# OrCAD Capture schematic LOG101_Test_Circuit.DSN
size A; title: LOG101, Precision LOGARITHMIC AND LOG RATIO AMPLIFIER; rev: 1.1; note: Datasheet: SBOS242B EVM: N/A
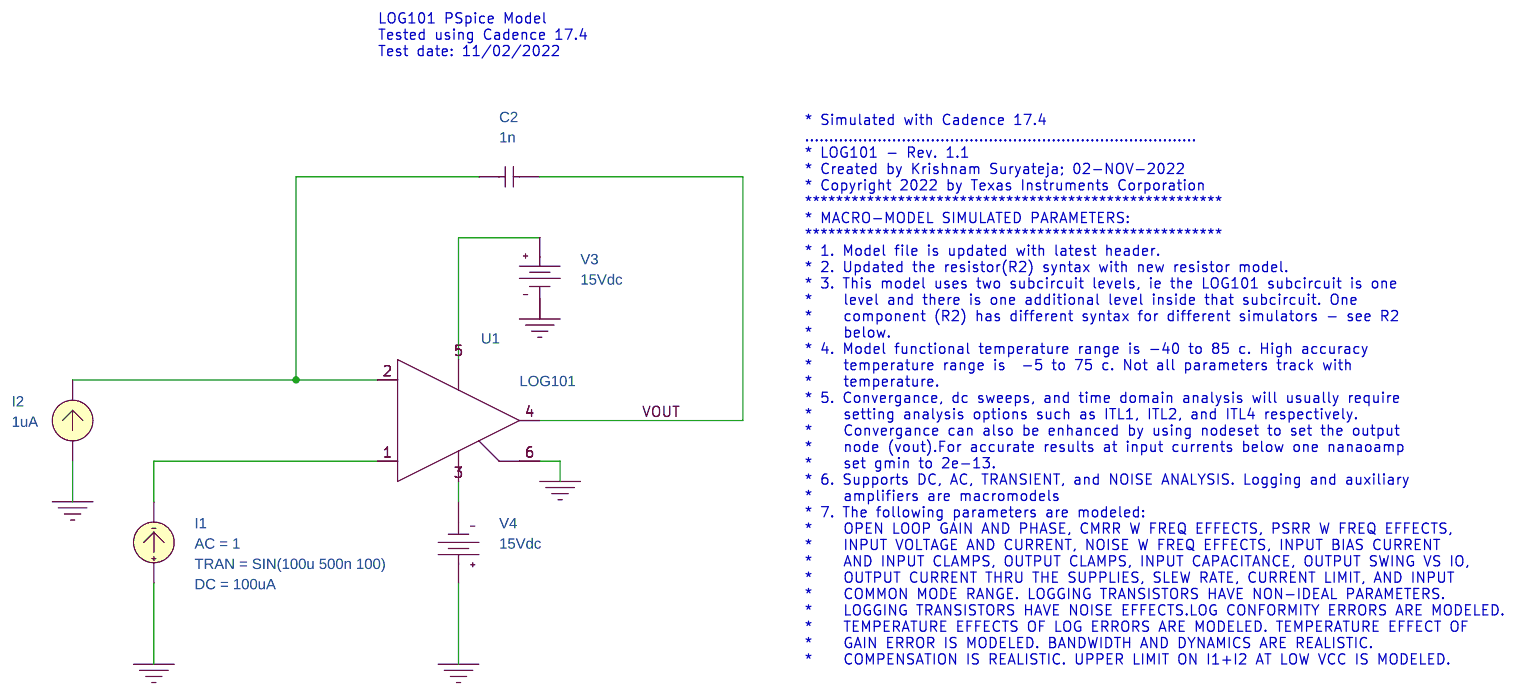
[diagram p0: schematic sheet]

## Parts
C2  1n  [RAD/CK05]
I1  ISRC
I2  IDC
U1  LOG101
V3  VDC
V4  VDC

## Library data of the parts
C2 = C
I1 = ISRC: AC: 1; DC: 100uA; TRAN: SIN(100u 500n 100)
I2 = IDC: DC: 1uA
U1 = LOG101
V3 V4 = VDC: DC: 15Vdc

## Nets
0: I1.1(+) I2.1(+) U1.6(GND) V3.1(-) V4.0(+)
VOUT: C2.2 U1.4(OUT)
N14289139: U1.5(V+) V3.0(+)
N14289210: U1.3(V-) V4.1(-)
N14289288: C2.1 I2.2(-) U1.2(I2)
N14289538: I1.2(-) U1.1(I1)

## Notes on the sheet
- LOG101 PSpice Model
  Tested using Cadence 17.4
  Test date: 11/02/2022
- * Simulated with Cadence 17.4
  .................................................................................
  * LOG101 - Rev. 1.1
  * Created by Krishnam Suryateja; 02-NOV-2022
  * Copyright 2022 by Texas Instruments Corporation
  ******************************************************
  * MACRO-MODEL SIMULATED PARAMETERS:
  ******************************************************
  * 1. Model file is updated with latest header.
  * 2. Updated the resistor(R2) syntax with new resistor model.
  * 3. This model uses two subcircuit levels, ie the LOG101 subcircuit is one
  *    level and there is one additional level inside that subcircuit. One
  *    component (R2) has different syntax for different simulators - see R2
  *    below.
  * 4. Model functional temperature range is -40 to 85 c. High accuracy
  *    temperature range is  -5 to 75 c. Not all parameters track with
  *    temperature.
  * 5. Convergance, dc sweeps, and time domain analysis will usually require
  *    setting analysis options such as ITL1, ITL2, and ITL4 respectively.
  *    Convergance can also be enhanced by using nodeset to set the output
  *    node (vout).For accurate results at input currents below one nanaoamp
  *    set gmin to 2e-13.
  * 6. Supports DC, AC, TRANSIENT, and NOISE ANALYSIS. Logging and auxiliary
  *    amplifiers are macromodels
  * 7. The following parameters are modeled:
  *    OPEN LOOP GAIN AND PHASE, CMRR W FREQ EFFECTS, PSRR W FREQ EFFECTS,
  *    INPUT VOLTAGE AND CURRENT, NOISE W FREQ EFFECTS, INPUT BIAS CURRENT
  *    AND INPUT CLAMPS, OUTPUT CLAMPS, INPUT CAPACITANCE, OUTPUT SWING VS IO,
  *    OUTPUT CURRENT THRU THE SUPPLIES, SLEW RATE, CURRENT LIMIT, AND INPUT
  *    COMMON MODE RANGE. LOGGING TRANSISTORS HAVE NON-IDEAL PARAMETERS.
  *    LOGGING TRANSISTORS HAVE NOISE EFFECTS.LOG CONFORMITY ERRORS ARE MODELED.
  *    TEMPERATURE EFFECTS OF LOG ERRORS ARE MODELED. TEMPERATURE EFFECT OF
  *    GAIN ERROR IS MODELED. BANDWIDTH AND DYNAMICS ARE REALISTIC.
  *    COMPENSATION IS REALISTIC. UPPER LIMIT ON I1+I2 AT LOW VCC IS MODELED.
